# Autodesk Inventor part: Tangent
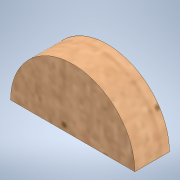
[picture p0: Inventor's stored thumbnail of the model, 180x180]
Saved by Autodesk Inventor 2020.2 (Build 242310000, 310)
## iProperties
Created: 2020-01
Part Number: Tangent
Material: Wood (Cherry)
Document SubType Name: Modeling
Designer: thira
Density: 0.63 g/cm^3
Appearance: Cherry - Natural Low Gloss
Author: thira
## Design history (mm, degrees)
sketch "Sketch1"
  geometry: L1 (-18, 0)-(18, 0); A1 r 18 centre (0, 0) between (18, 0) and (-18, 0); 3 further points
  constraints: 3 coincident, 2 end point, 2 point on circle, 1 centre point, 1 horizontal, 1 midpoint
  dimensions: "d0" = 18 radius of A1
extrude "Extrusion1" new body sketch "Sketch1" distance "d1" = 10; taper "d2" = 0 deg
body "Solid1"
